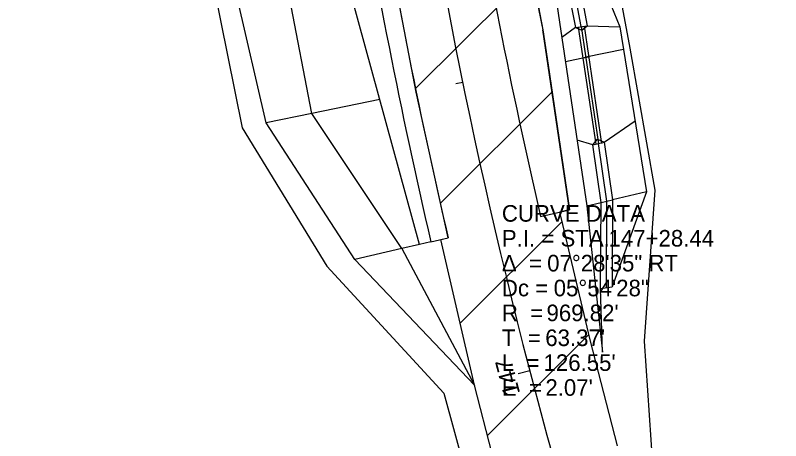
# Model space of a CAD drawing. Extents: x 195197 to 195502, y 336876 to 337459.
# Drawn here: x 195268.9 to 195398, y 337022.7 to 337094.6 of the extents above; entities that cross this region are included whole.
import ezdxf

# ---------------------------------------------------------------- set-up
doc = ezdxf.new("R2010")
doc.units = 0
for name, color, linetype in [('_CIVIL_CONSTRUCTION', 7, 'Continuous'), ('DR_P_Cells', 7, 'Continuous'), ('DR_P_Headwall', 7, 'Continuous'), ('DT_X_Contour_Major', 7, 'Continuous'), ('DT_X_Island', 7, 'Continuous'), ('DT_X_Triangles', 7, 'Continuous'), ('DT_X_Void', 7, 'Continuous'), ('GK_Drainage_Nodes', 7, 'Continuous'), ('MD_P_Surface_Finished_Grade', 7, 'Continuous'), ('PV_P_Shoulder', 7, 'Continuous'), ('SC_Scratch1', 7, 'Continuous'), ('SH_Major_Grid_Line', 7, 'Continuous')]:
    doc.layers.add(name, color=color, linetype=linetype)

msp = doc.modelspace()

# ---------------------------------------------------------------- linework, layer by layer
at = {"layer": '_CIVIL_CONSTRUCTION'}
for points in [[(195287.97, 337251.38), (195291.95, 337226.7), (195292.97, 337201.54), (195292.2, 337181.16), (195292.01, 337176.07), (195280.02, 337163.48), (195272.33, 337157.95), (195268.88, 337148.33), (195288.8, 337131.36), (195292.54, 337124.96), (195302.23, 337099.91), (195307.11, 337075.58), (195321.43, 337052.24), (195341.13, 337030.76), (195347.82, 337006.27), (195355.4, 336981.71), (195364.48, 336957.43), (195370.64, 336943.15), (195384.3, 336949.34)], [(195384.3, 336949.34), (195397.97, 336955.53), (195391.34, 336968.43), (195383.81, 336991.35), (195376.66, 337014.55), (195375.01, 337039.55), (195376.79, 337065.03), (195372.56, 337089.05), (195368.12, 337112.86), (195370.07, 337138.01), (195373.6, 337153.77), (195378.92, 337164.76)]]:
    msp.add_lwpolyline(points, dxfattribs=at)
at = {"layer": 'DR_P_Cells'}
msp.add_line((195338.96, 337056.31), (195341.89, 337056.99), dxfattribs=at)
for radius, start in [(977.82, 189.13956), (980.82, 189.13959)]:
    msp.add_arc((196294.35, 337278.21), radius, start, 193.07582, dxfattribs=at)
at = {"layer": 'DR_P_Headwall'}
for p, q in [((195344.34, 337083.22), (195343.16, 337082.98)), ((195355.65, 337034.53), (195353.71, 337034.02))]:
    msp.add_line(p, q, dxfattribs=at)
at = {"layer": 'DT_X_Contour_Major'}
for points in [[(195364.32, 337092.66), (195360.75, 337111.55), (195363.4, 337136.93), (195365.01, 337152.39), (195366.35, 337161.04)], [(195368.57, 337048.59), (195368.65, 337063.21), (195367.24, 337072.94)]]:
    msp.add_lwpolyline(points, dxfattribs=at)
at = {"layer": 'DT_X_Island'}
for p, q in [((195362.34, 337061.74), (195357.84, 337092.15)), ((195357.47, 337060.61), (195362.34, 337061.74))]:
    msp.add_line(p, q, dxfattribs=at)
for radius, end in [(961.82, 193.07582), (954.82, 191.23696)]:
    msp.add_arc((196294.35, 337278.21), radius, 189.13948, end, dxfattribs=at)
at = {"layer": 'DT_X_Triangles'}
for p, q in [((195363.83, 337092.59), (195366.76, 337072.8)), ((195364.82, 337092.73), (195367.75, 337072.95))]:
    msp.add_line(p, q, dxfattribs=at)
at = {"layer": 'DT_X_Void'}
for p, q in [((195336.39, 337082.19), (195356.01, 337101.81)), ((195340.61, 337062.84), (195359.4, 337081.63)), ((195343.91, 337042.57), (195361.05, 337059.71)), ((195348.52, 337023.61), (195365.55, 337040.64))]:
    msp.add_line(p, q, dxfattribs=at)
msp.add_lwpolyline([(195352.31, 337008.93), (195346.32, 337032.1), (195340.67, 337056.71), (195341.89, 337056.99), (195336.5, 337081.62), (195331.75, 337106.37), (195327.61, 337131.16), (195325.23, 337145.97), (195347.93, 337149.63), (195350.32, 337134.82), (195354.39, 337110.41), (195357.84, 337092.15), (195358.72, 337086.18), (195362.34, 337061.74), (195360.67, 337061.36), (195360.87, 337060.45), (195365.75, 337039.78), (195370.38, 337021.87)], dxfattribs=at)
at = {"layer": 'GK_Drainage_Nodes'}
for p, q in [((195337.02, 337055.86), (195324.3, 337102.59)), ((195338.96, 337056.31), (195337.02, 337055.86))]:
    msp.add_line(p, q, dxfattribs=at)
at = {"layer": 'PV_P_Shoulder'}
for p, q in [((195359.77, 337111.37), (195363.33, 337092.51)), ((195361.74, 337111.72), (195365.31, 337092.81)), ((195362.95, 337111.94), (195370.86, 337092.63)), ((195318.87, 337078), (195314.03, 337103.21)), ((195311.19, 337076.42), (195305.34, 337101.66)), ((195359.71, 337099.93), (195365.26, 337062.42)), ((195363.33, 337092.51), (195361.06, 337090.82)), ((195363.33, 337092.51), (195364.44, 337092.09)), ((195364.44, 337092.09), (195365.31, 337092.81)), ((195365.31, 337092.81), (195370.86, 337092.63)), ((195370.86, 337092.63), (195375.33, 337064.76)), ((195371.47, 337088.79), (195365.09, 337087.48)), ((195361.66, 337086.78), (195365.09, 337087.48)), ((195330.35, 337080.35), (195318.87, 337078)), ((195318.87, 337078), (195311.19, 337076.42)), ((195334.09, 337055.18), (195318.87, 337078)), ((195326.16, 337053.34), (195311.19, 337076.42)), ((195368.22, 337073.16), (195373.4, 337076.78)), ((195366.26, 337072.73), (195367.08, 337073.66)), ((195367.08, 337073.66), (195368.22, 337073.16)), ((195366.26, 337072.73), (195363.65, 337073.47)), ((195367.67, 337062.98), (195366.26, 337072.73)), ((195368.22, 337073.16), (195369.62, 337063.43)), ((195375.33, 337064.76), (195369.57, 337048.73)), ((195375.33, 337064.76), (195369.62, 337063.43)), ((195369.62, 337063.43), (195369.57, 337048.73)), ((195365.26, 337062.42), (195367.67, 337062.98)), ((195365.26, 337062.42), (195367.89, 337037.7)), ((195367.59, 337048.45), (195367.67, 337062.98)), ((195337.02, 337055.86), (195334.09, 337055.18)), ((195334.09, 337055.18), (195326.16, 337053.34)), ((195334.09, 337055.18), (195346.32, 337032.1)), ((195326.16, 337053.34), (195346.32, 337032.1)), ((195367.89, 337037.7), (195367.59, 337048.45))]:
    msp.add_line(p, q, dxfattribs=at)
at = {"layer": 'SC_Scratch1'}
msp.add_arc((196294.35, 337278.21), 969.82, 189.13948, 196.61598, dxfattribs=at)
at = {"layer": 'SH_Major_Grid_Line'}
for p, q in [((195363.33, 337092.51), (195365.31, 337092.81)), ((195364.32, 337092.66), (195367.25, 337072.87)), ((195364.6, 337087.38), (195365.58, 337087.58)), ((195366.26, 337072.73), (195368.22, 337073.16)), ((195367.67, 337062.98), (195369.62, 337063.43)), ((195367.59, 337048.45), (195369.57, 337048.73))]:
    msp.add_line(p, q, dxfattribs=at)

# ---------------------------------------------------------------- texts
at = {"layer": 'DR_P_Headwall'}
msp.add_text('147', height=2.8, rotation=104.5528, dxfattribs=at).set_placement((195354.04, 337030.76))
at = {"layer": 'MD_P_Surface_Finished_Grade'}
for s, p in [('CURVE DATA', (195350.94, 337059.73)), ('P.I. = STA. ', (195350.94, 337055.53)), ('147+28.44', (195368.93, 337055.53)), ('Δ  = ', (195350.94, 337051.33)), ('07°28\'35" RT', (195358.58, 337051.33)), ('Dc = ', (195350.94, 337047.13)), ('05°54\'28"', (195359.68, 337047.13)), ('R  = ', (195350.94, 337042.93)), ("969.82'", (195358.47, 337042.93)), ('T  = ', (195350.94, 337038.73)), ("63.37'", (195358.26, 337038.73)), ('L  = ', (195350.94, 337034.53)), ("126.55'", (195357.97, 337034.53)), ('E  = ', (195350.94, 337030.33)), ("2.07'", (195358.28, 337030.33))]:
    msp.add_text(s, height=2.8, dxfattribs=at).set_placement(p)

doc.saveas('drawing.dxf')
